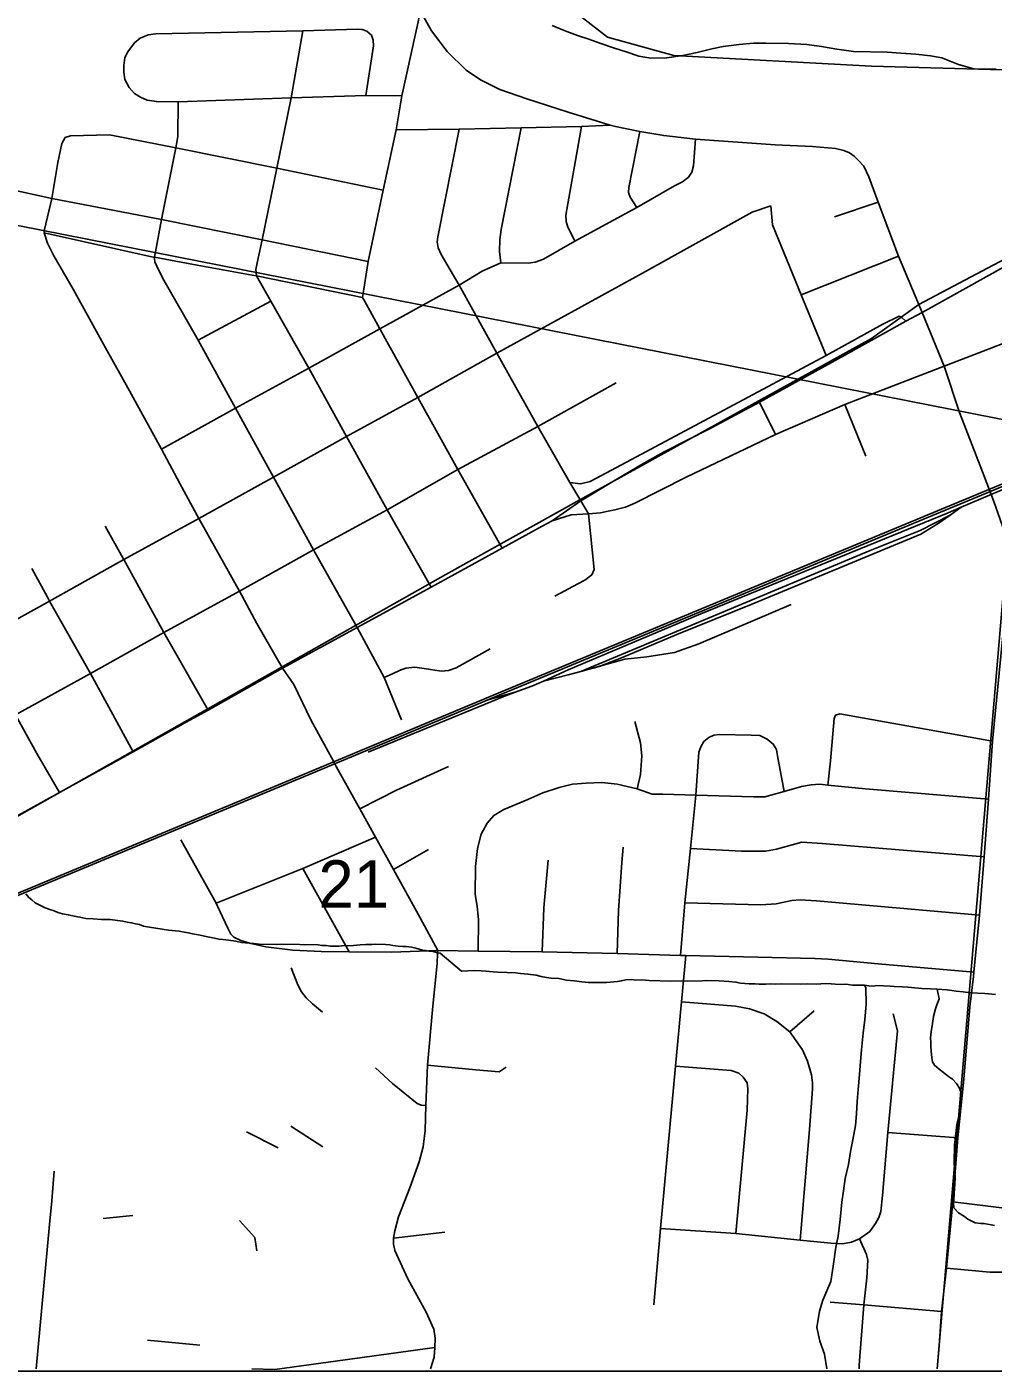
# Model space of a CAD drawing. Extents: x 0 to 34, y 0 to 22.
# Drawn here: x 5.806 to 6.657, y 14 to 15.184 of the extents above; entities that cross this region are included whole.
import ezdxf

# ---------------------------------------------------------------- set-up
doc = ezdxf.new("R2010")
doc.units = 0
for name, color, linetype in [('GM_X_City_Street', 7, 'Continuous'), ('GM_X_County_Road', 7, 'Continuous'), ('GM_X_Major_River', 7, 'Continuous'), ('GM_X_Minor_River', 7, 'Continuous'), ('GM_X_Rail_Line', 7, 'Continuous'), ('GM_X_Section', 7, 'Continuous'), ('GM_X_Section_Text', 7, 'Continuous'), ('SH_Data', 7, 'Continuous')]:
    doc.layers.add(name, color=color, linetype=linetype)

msp = doc.modelspace()

# ---------------------------------------------------------------- linework, layer by layer
at = {"layer": 'GM_X_City_Street'}
for p, q in [((6.5177, 15.017), (6.5561, 15.0299)), ((5.8215, 15.0029), (5.9175, 14.9815)), ((6.4882, 14.9483), (6.574, 14.9822)), ((5.9562, 14.9744), (6.0046, 14.9656)), ((5.9569, 14.9084), (6.0211, 14.9426)), ((6.4657, 14.8253), (6.4514, 14.8537)), ((6.5453, 14.8062), (6.5268, 14.8515)), ((5.8895, 14.7186), (5.8752, 14.7444)), ((5.8243, 14.6819), (5.8105, 14.7072)), ((6.5222, 14.579), (6.6568, 14.555)), ((6.129, 14.442), (6.16, 14.4597)), ((6.0901, 14.3694), (6.0491, 14.4428)), ((6.4781, 14.2988), (6.4996, 14.3175)), ((6.0387, 14.2159), (6.0669, 14.1975)), ((5.9996, 14.2109), (6.0275, 14.1967)), ((6.5647, 14.2103), (6.6263, 14.2054)), ((5.8734, 14.1345), (5.8996, 14.1371)), ((6.1291, 14.117), (6.1743, 14.1224)), ((5.9123, 14.0272), (5.9584, 14.0229))]:
    msp.add_line(p, q, dxfattribs=at)
for points in [[(6.2249, 14.7251), (6.1857, 14.7943), (6.1505, 14.8578), (6.1171, 14.9182), (6.1034, 14.9431), (6.1017, 14.9458), (6.1069, 14.9777), (6.1199, 15.0406), (6.1313, 15.0935), (6.1364, 15.1237), (6.153, 15.1983)], [(6.3248, 15.0966), (6.32, 15.0976), (6.283, 15.1092), (6.2466, 15.121), (6.2227, 15.1293), (6.2058, 15.1378), (6.193, 15.1462), (6.1764, 15.1625), (6.1626, 15.1807), (6.153, 15.1983)], [(5.8916, 15.1445), (5.8914, 15.1502), (5.8925, 15.1574), (5.8951, 15.1623), (5.9008, 15.1704), (5.906, 15.1745), (5.9131, 15.1773), (5.9197, 15.1782), (6.0493, 15.1809), (6.0974, 15.1822), (6.1015, 15.1819), (6.1055, 15.1805), (6.1096, 15.177), (6.1113, 15.1727), (6.1115, 15.1675), (6.1046, 15.1238)], [(6.1622, 14.6908), (6.1235, 14.7588), (6.0877, 14.8234), (6.0546, 14.8837), (6.0211, 14.9426), (6.0085, 14.9649), (6.0077, 14.9706), (6.009, 14.9763), (6.0134, 14.9966), (6.0262, 15.0599), (6.039, 15.1218), (6.0493, 15.1809)], [(5.8916, 15.1445), (5.8925, 15.1381), (5.8962, 15.1309), (5.9009, 15.1255), (5.9061, 15.1225), (5.9121, 15.1199), (5.9202, 15.1185), (5.9395, 15.1183), (6.039, 15.1218), (6.1046, 15.1238), (6.1364, 15.1237)], [(5.9186, 14.9803), (5.9185, 14.9813), (5.9246, 15.0145), (5.9373, 15.0778), (5.9385, 15.0841), (5.9391, 15.088), (5.9395, 15.1183)], [(5.8217, 15.0059), (5.828, 15.0331), (5.8335, 15.0647), (5.8368, 15.0815), (5.8399, 15.0868), (5.8445, 15.0882)], [(5.8445, 15.0882), (5.8788, 15.0892), (5.9373, 15.0778), (6.0262, 15.0599), (6.1199, 15.0406)], [(6.1313, 15.0935), (6.1869, 15.0941), (6.2415, 15.0953), (6.2948, 15.0966), (6.32, 15.0976)], [(6.301, 14.7554), (6.2942, 14.7667), (6.2843, 14.7828), (6.2561, 14.8323), (6.2201, 14.8968), (6.1869, 14.9569), (6.171, 14.9839), (6.1685, 14.9898), (6.1676, 14.995), (6.1682, 14.9994), (6.1869, 15.0941)], [(6.2236, 14.9763), (6.2224, 14.9863), (6.2229, 14.9971), (6.2238, 15.0059), (6.2415, 15.0953)], [(6.2889, 14.9955), (6.2852, 15.0028), (6.2826, 15.0079), (6.2811, 15.013), (6.2809, 15.0184), (6.2948, 15.0966)], [(6.6142, 14.8854), (6.5947, 14.9327), (6.574, 14.9822), (6.5561, 15.0299), (6.5479, 15.0523), (6.5435, 15.0616), (6.5387, 15.0667), (6.5348, 15.0705), (6.5308, 15.0735), (6.5257, 15.0754), (6.5184, 15.0771), (6.4982, 15.0789), (6.4652, 15.0805), (6.395, 15.0853), (6.3672, 15.0885), (6.346, 15.0921), (6.3248, 15.0966)], [(6.3435, 15.0251), (6.3377, 15.0343), (6.3361, 15.0385), (6.3364, 15.0428), (6.346, 15.0921)], [(5.9246, 14.8122), (5.9898, 14.8483), (6.0546, 14.8837), (6.1171, 14.9182), (6.1869, 14.9569), (6.2071, 14.969), (6.2236, 14.9763), (6.2476, 14.9761), (6.2538, 14.9769), (6.2611, 14.9796), (6.2889, 14.9955), (6.3435, 15.0251), (6.3766, 15.0442), (6.3836, 15.0479), (6.3891, 15.052), (6.3919, 15.0564), (6.3935, 15.062), (6.395, 15.0853)], [(6.9067, 15.0855), (6.8847, 15.0834), (6.8704, 15.082), (6.8594, 15.0779), (6.7869, 15.0396), (6.7593, 15.0237), (6.7279, 15.0059), (6.687, 14.9841), (6.5947, 14.9327), (6.5803, 14.9251), (6.5268, 14.8951), (6.4514, 14.8537), (6.4086, 14.8309), (6.3668, 14.8095), (6.3502, 14.8001), (6.3244, 14.7851), (6.2942, 14.7667), (6.2688, 14.7491)], [(5.7623, 15.0474), (5.828, 15.0331), (5.9246, 15.0145), (6.0134, 14.9966), (6.1069, 14.9777)], [(5.7606, 14.6422), (5.8261, 14.6785), (5.8914, 14.7152), (5.9576, 14.7513), (6.0234, 14.7875), (6.0877, 14.8234), (6.1505, 14.8578), (6.2201, 14.8968), (6.3483, 14.9674), (6.445, 15.0211), (6.4614, 15.0267)], [(6.5101, 14.8947), (6.4882, 14.9483), (6.4631, 15.01), (6.4614, 15.0267)], [(6.0313, 14.6194), (6.0088, 14.6588), (5.9933, 14.6873), (5.9576, 14.7513), (5.9409, 14.7821), (5.9246, 14.8122), (5.8966, 14.8637), (5.8753, 14.9015), (5.8468, 14.9533), (5.83, 14.9826), (5.8242, 14.9937), (5.8215, 15.0029), (5.8217, 15.0059)], [(5.9175, 14.9815), (5.9185, 14.9813), (5.9562, 14.9744)], [(6.0971, 14.6553), (6.0587, 14.7237), (6.0234, 14.7875), (5.9898, 14.8483), (5.9569, 14.9084), (5.9256, 14.9633), (5.9205, 14.9735), (5.9189, 14.9772), (5.9186, 14.9803)], [(6.0046, 14.9656), (6.0085, 14.9649), (6.1017, 14.9458)], [(6.2843, 14.7828), (6.2938, 14.7818), (6.3022, 14.7838), (6.33, 14.7984), (6.5101, 14.8947), (6.5603, 14.9223), (6.5746, 14.9294), (6.5768, 14.9284), (6.5803, 14.9251)], [(6.6399, 14.3476), (6.6404, 14.3515), (6.6452, 14.4018), (6.6495, 14.453), (6.6532, 14.5039), (6.6568, 14.555), (6.667, 14.6598), (6.6712, 14.7093), (6.6714, 14.7157), (6.6708, 14.7242), (6.6673, 14.7393), (6.6579, 14.7661), (6.648, 14.7923), (6.6276, 14.8447), (6.6142, 14.8854)], [(5.6319, 14.4874), (5.6747, 14.5115), (5.717, 14.535), (5.76, 14.5587), (5.7961, 14.5781), (5.8621, 14.6147), (5.9268, 14.6507), (5.9933, 14.6873), (6.0587, 14.7237), (6.1235, 14.7588), (6.1857, 14.7943), (6.2561, 14.8323), (6.3253, 14.8707)], [(6.2713, 14.6828), (6.2916, 14.6936), (6.2977, 14.697), (6.3038, 14.7015), (6.3059, 14.7063), (6.301, 14.7554)], [(5.9657, 14.5824), (5.9268, 14.6507), (5.8914, 14.7152), (5.8895, 14.7186)], [(5.8999, 14.5457), (5.8621, 14.6147), (5.8261, 14.6785), (5.8243, 14.6819)], [(6.1362, 14.5739), (6.1208, 14.6111), (6.0971, 14.6553)], [(6.1208, 14.6111), (6.1289, 14.6147), (6.1345, 14.6174), (6.14, 14.6193), (6.1478, 14.6202), (6.1561, 14.619), (6.1711, 14.6166), (6.1775, 14.6173), (6.1843, 14.6195), (6.2143, 14.6364)], [(6.0787, 14.5327), (6.0764, 14.5369), (6.0563, 14.5739), (6.0412, 14.605), (6.0313, 14.6194)], [(6.3438, 14.513), (6.3466, 14.5256), (6.3479, 14.5421), (6.3468, 14.5536), (6.3418, 14.5722)], [(6.5117, 14.5162), (6.5141, 14.5377), (6.5174, 14.575), (6.5186, 14.578), (6.5222, 14.579)], [(6.3955, 14.5075), (6.3982, 14.5453), (6.3997, 14.55), (6.4024, 14.5548), (6.407, 14.5583), (6.4114, 14.5603), (6.4162, 14.5608), (6.4442, 14.5604), (6.4517, 14.56), (6.4584, 14.5568), (6.4636, 14.5524), (6.4664, 14.5476), (6.4674, 14.542), (6.4732, 14.5106)], [(6.1679, 14.3686), (6.168, 14.3705), (6.1527, 14.3993), (6.129, 14.442), (6.1131, 14.4705), (6.0995, 14.4955), (6.0787, 14.5327)], [(6.0995, 14.4955), (6.1316, 14.5117), (6.1775, 14.5328)], [(6.2038, 14.3701), (6.2041, 14.3979), (6.2028, 14.4093), (6.2009, 14.4203), (6.2014, 14.4445), (6.2032, 14.4603), (6.2064, 14.473), (6.2116, 14.4827), (6.2174, 14.4895), (6.2263, 14.4947), (6.2473, 14.5037), (6.2605, 14.5094), (6.2751, 14.5143), (6.2867, 14.517), (6.2988, 14.5181), (6.3127, 14.5185), (6.3261, 14.5172), (6.3438, 14.513), (6.357, 14.5084), (6.3664, 14.5082), (6.3955, 14.5075), (6.4462, 14.5059), (6.4562, 14.5061), (6.4646, 14.5083), (6.4732, 14.5106), (6.4884, 14.5152), (6.4969, 14.5165), (6.5046, 14.5171), (6.5117, 14.5162), (6.5449, 14.5129), (6.6532, 14.5039)], [(6.3819, 14.3663), (6.3856, 14.4127), (6.3907, 14.4604), (6.3955, 14.5075)], [(5.9741, 14.4096), (5.9729, 14.4122), (5.9418, 14.4682)], [(5.9729, 14.4122), (6.0491, 14.4428), (6.1131, 14.4705)], [(6.3262, 14.3679), (6.3274, 14.4057), (6.3302, 14.448), (6.3313, 14.4616)], [(6.3907, 14.4604), (6.4356, 14.4581), (6.4569, 14.458), (6.4666, 14.46), (6.4751, 14.4622), (6.4887, 14.4659), (6.5067, 14.4648), (6.6495, 14.453)], [(6.2602, 14.3694), (6.2616, 14.4083), (6.2652, 14.4503)], [(6.3856, 14.4127), (6.4526, 14.4109), (6.4663, 14.4118), (6.4801, 14.4145), (6.4873, 14.4152), (6.5016, 14.4144), (6.6452, 14.4018)], [(5.9946, 14.3793), (5.9883, 14.3823), (5.9857, 14.3851), (5.9831, 14.3903), (5.9741, 14.4096)], [(5.9946, 14.3793), (6.0033, 14.3768), (6.0167, 14.3738), (6.0405, 14.371), (6.0654, 14.3696), (6.0901, 14.3694), (6.1272, 14.3691), (6.168, 14.3705), (6.2038, 14.3701), (6.2602, 14.3694), (6.3262, 14.3679), (6.3819, 14.3663), (6.3867, 14.3662), (6.4499, 14.3648), (6.5003, 14.3634), (6.5121, 14.3629), (6.5559, 14.3588), (6.6404, 14.3515)], [(6.1617, 14.0019), (6.165, 14.0123), (6.1655, 14.0208), (6.1658, 14.0289), (6.1647, 14.037), (6.1578, 14.0518), (6.1416, 14.0812), (6.1303, 14.1063), (6.129, 14.1118), (6.1291, 14.117), (6.1303, 14.1237), (6.1336, 14.1359), (6.1434, 14.1615), (6.1518, 14.1844), (6.1553, 14.1975), (6.1571, 14.2121), (6.1576, 14.2341), (6.159, 14.2696), (6.1637, 14.3214), (6.1675, 14.359), (6.1679, 14.3686)], [(6.3585, 14.0584), (6.3642, 14.1257), (6.3776, 14.2687), (6.3829, 14.3253), (6.3867, 14.3662)], [(6.0388, 14.3554), (6.0447, 14.3403), (6.0479, 14.3341), (6.0523, 14.3288), (6.0578, 14.3235), (6.0665, 14.3163)], [(6.6081, 14.0019), (6.6097, 14.0223), (6.6118, 14.0525), (6.6163, 14.0907), (6.6217, 14.149), (6.6263, 14.2054), (6.6316, 14.2572), (6.6368, 14.321), (6.6399, 14.3476)], [(6.4873, 14.1155), (6.4957, 14.2129), (6.4982, 14.2484), (6.4982, 14.2539), (6.4972, 14.2611), (6.4939, 14.2732), (6.4894, 14.283), (6.4781, 14.2988), (6.4669, 14.308), (6.4555, 14.3148), (6.4428, 14.3193), (6.4303, 14.3214), (6.3829, 14.3253)], [(6.3642, 14.1257), (6.4308, 14.1211), (6.4873, 14.1155), (6.5144, 14.1128), (6.5246, 14.1121), (6.5325, 14.1136), (6.5396, 14.1164), (6.5487, 14.1231), (6.5538, 14.1302), (6.5566, 14.1353), (6.5583, 14.1406), (6.5599, 14.1548), (6.5647, 14.2103), (6.573, 14.2997), (6.5694, 14.3147)], [(6.1131, 14.2672), (6.1283, 14.2535), (6.1499, 14.2359), (6.1534, 14.2344), (6.1576, 14.2341)], [(6.159, 14.2696), (6.2015, 14.2653), (6.2223, 14.2638), (6.2284, 14.2678)], [(6.4308, 14.1211), (6.4405, 14.2298), (6.4413, 14.2488), (6.4405, 14.2539), (6.437, 14.2591), (6.4333, 14.2626), (6.4266, 14.2649), (6.3776, 14.2687)], [(5.8142, 14.0019), (5.826, 14.1293), (5.8281, 14.1501), (5.8303, 14.1763)], [(6.6217, 14.149), (6.7966, 14.1277), (6.7983, 14.1272)], [(5.9933, 14.1326), (6.0068, 14.1178), (6.0086, 14.106)], [(6.5393, 14.0019), (6.5394, 14.0053), (6.5435, 14.0584), (6.546, 14.0823), (6.5469, 14.0978), (6.5459, 14.1026), (6.5396, 14.1164)], [(6.6163, 14.0907), (6.6545, 14.0873), (6.6654, 14.0872), (6.6734, 14.0884), (6.6933, 14.0946), (6.7014, 14.0949), (6.7482, 14.0907), (6.7534, 14.0894), (6.7583, 14.0868), (6.7638, 14.08)], [(6.5137, 14.0606), (6.5435, 14.0584), (6.6118, 14.0525)], [(6.0044, 14.002), (6.0246, 14.0014), (6.1655, 14.0208)]]:
    msp.add_lwpolyline(points, dxfattribs=at)
at = {"layer": 'GM_X_County_Road'}
for points in [[(6.3183, 14.7576), (6.3242, 14.7589), (6.3334, 14.7613), (6.3417, 14.7648), (6.387, 14.7877), (6.4657, 14.8253), (6.5268, 14.8515), (6.6142, 14.8854), (6.6921, 14.9153)], [(6.26, 14.7443), (6.2688, 14.7491), (6.2856, 14.7543), (6.301, 14.7554), (6.3114, 14.7562), (6.3183, 14.7576)], [(5.946, 14.5714), (5.9657, 14.5824), (6.0313, 14.6194), (6.0971, 14.6553), (6.1622, 14.6908), (6.2249, 14.7251), (6.26, 14.7443)], [(5.7198, 14.7161), (5.7268, 14.7035), (5.7432, 14.6736), (5.7606, 14.6422), (5.7811, 14.6051), (5.7961, 14.5781), (5.8149, 14.5442), (5.8348, 14.5098)], [(5.3074, 14.2462), (5.3154, 14.251), (5.329, 14.2582), (5.3473, 14.2671), (5.4124, 14.2985), (5.4668, 14.3252), (5.5266, 14.354), (5.5858, 14.3822), (5.6268, 14.4024), (5.6685, 14.423), (5.7094, 14.4428), (5.7337, 14.4547), (5.7485, 14.4622), (5.8348, 14.5098), (5.8999, 14.5457), (5.946, 14.5714)]]:
    msp.add_lwpolyline(points, dxfattribs=at)
at = {"layer": 'GM_X_Major_River'}
msp.add_lwpolyline([(6.2688, 15.1856), (6.2794, 15.1812), (6.2911, 15.1768), (6.3012, 15.1735), (6.311, 15.1699), (6.3238, 15.1655), (6.334, 15.1622), (6.3453, 15.1586), (6.3559, 15.1569), (6.37, 15.157), (6.384, 15.159), (6.3966, 15.1618), (6.4096, 15.1649), (6.4195, 15.167), (6.4335, 15.1687), (6.4461, 15.17), (6.4571, 15.1701), (6.4772, 15.1697), (6.4931, 15.1687), (6.506, 15.1669), (6.5196, 15.1647), (6.5343, 15.1625), (6.5639, 15.162), (6.5761, 15.1613), (6.5893, 15.1603), (6.6022, 15.1589), (6.612, 15.1572), (6.6267, 15.1512), (6.6403, 15.1475), (6.6498, 15.147), (6.66, 15.1472)], dxfattribs=at)
at = {"layer": 'GM_X_Minor_River'}
for points in [[(5.8053, 14.4205), (5.8079, 14.4174), (5.8105, 14.4151), (5.8135, 14.4127), (5.818, 14.4103), (5.8222, 14.4083), (5.8263, 14.4067), (5.8301, 14.4055), (5.8335, 14.4042), (5.8376, 14.403), (5.8426, 14.4021), (5.8479, 14.4008), (5.8528, 14.4), (5.8581, 14.3987), (5.8646, 14.3985), (5.8718, 14.398), (5.8794, 14.3978), (5.8859, 14.3969), (5.8908, 14.3964), (5.8946, 14.3955), (5.8984, 14.3951), (5.9018, 14.3942), (5.9053, 14.3934), (5.909, 14.3921), (5.914, 14.3912), (5.931, 14.3885), (5.9402, 14.3876)], [(5.9402, 14.3876), (5.9447, 14.3867), (5.9485, 14.3862), (5.9519, 14.3854), (5.9572, 14.3845), (5.9641, 14.3828), (5.9671, 14.3823), (5.9713, 14.3815), (5.9751, 14.3806), (5.9789, 14.3802), (5.9838, 14.3797), (5.9903, 14.3787), (5.9952, 14.3775), (6.002, 14.3769), (6.0062, 14.3768), (6.0108, 14.3763), (6.0264, 14.376), (6.0302, 14.3762), (6.0626, 14.3755), (6.066, 14.375), (6.0698, 14.3749), (6.0733, 14.3744), (6.0809, 14.3743), (6.0836, 14.3746), (6.087, 14.3749), (6.0904, 14.3748), (6.0939, 14.3751), (6.0969, 14.3754), (6.0996, 14.3757), (6.1046, 14.376), (6.1099, 14.3758), (6.1129, 14.3761), (6.1221, 14.3759), (6.1259, 14.3755), (6.1285, 14.375), (6.1331, 14.3745), (6.1373, 14.374), (6.1403, 14.374), (6.1449, 14.3735), (6.1487, 14.3726), (6.1547, 14.3709), (6.1574, 14.3705), (6.1604, 14.37), (6.1639, 14.3696), (6.1669, 14.3687), (6.1703, 14.3683)], [(6.1703, 14.3683), (6.189, 14.3524), (6.1947, 14.3527), (6.2008, 14.3529), (6.2062, 14.3528), (6.2103, 14.3523), (6.2168, 14.3517), (6.221, 14.3516), (6.2293, 14.3511), (6.2365, 14.3509), (6.2411, 14.3504), (6.2475, 14.3498), (6.2547, 14.3489), (6.2593, 14.3477), (6.2638, 14.3468), (6.268, 14.3463), (6.2748, 14.3458), (6.2816, 14.3444), (6.2881, 14.3439), (6.2949, 14.343), (6.301, 14.3424), (6.3166, 14.3424), (6.3265, 14.3433), (6.3299, 14.344), (6.3337, 14.3447), (6.3391, 14.3449), (6.3425, 14.3445), (6.3478, 14.3447), (6.3543, 14.3442), (6.3733, 14.3437), (6.3851, 14.3438), (6.3885, 14.3437), (6.4014, 14.3438), (6.4048, 14.3441), (6.4159, 14.3438), (6.4246, 14.3432), (6.4307, 14.3427), (6.4348, 14.3418), (6.4424, 14.3412), (6.4477, 14.3411), (6.4512, 14.341), (6.4572, 14.3409), (6.4611, 14.3411), (6.4656, 14.341), (6.4706, 14.3413), (6.488, 14.3409), (6.4938, 14.3411), (6.5017, 14.3409), (6.5055, 14.3412), (6.5097, 14.3415), (6.5147, 14.3413), (6.5181, 14.3409), (6.5238, 14.3407), (6.5276, 14.341), (6.5333, 14.3401), (6.5439, 14.3399), (6.5477, 14.3394), (6.5519, 14.3393), (6.5549, 14.3396), (6.5667, 14.3393), (6.5701, 14.3388), (6.5774, 14.3387), (6.5823, 14.3382), (6.5853, 14.3381), (6.5944, 14.3371), (6.602, 14.3369), (6.6081, 14.3364), (6.6123, 14.3363), (6.6168, 14.3358), (6.621, 14.3353), (6.6248, 14.3348), (6.6309, 14.3343), (6.6373, 14.3334), (6.6499, 14.3327), (6.6593, 14.3317)], [(6.5439, 14.3399), (6.5452, 14.3379), (6.5456, 14.323), (6.5442, 14.3097), (6.5429, 14.2976), (6.5414, 14.2832), (6.5405, 14.2729), (6.5395, 14.2612), (6.5385, 14.2482), (6.5375, 14.2376), (6.5369, 14.2266), (6.536, 14.2163), (6.5338, 14.2038), (6.5317, 14.1936), (6.53, 14.1819), (6.5271, 14.1697), (6.5254, 14.1587), (6.524, 14.1489), (6.5226, 14.1337), (6.5208, 14.1189), (6.5187, 14.1091), (6.5165, 14.0924), (6.5143, 14.0791), (6.5072, 14.0625), (6.5043, 14.0527), (6.5021, 14.0383), (6.5046, 14.0264), (6.5089, 14.0149), (6.5109, 14.0019)], [(6.6081, 14.3364), (6.6098, 14.328), (6.6078, 14.3227), (6.6065, 14.3193), (6.6049, 14.3125), (6.6039, 14.3064), (6.6026, 14.2989), (6.6021, 14.2936), (6.6024, 14.2894), (6.6023, 14.2859), (6.6026, 14.2821), (6.6032, 14.276), (6.6039, 14.2726), (6.6057, 14.2695), (6.6098, 14.266), (6.6135, 14.2632), (6.618, 14.2597), (6.6214, 14.2573), (6.6251, 14.2535), (6.6276, 14.2492), (6.6291, 14.245), (6.6297, 14.24), (6.6287, 14.2305), (6.6258, 14.22), (6.6253, 14.2169), (6.6243, 14.2071), (6.6239, 14.2037), (6.6234, 14.1995), (6.623, 14.1832), (6.6232, 14.1786), (6.6238, 14.1714), (6.6236, 14.1641), (6.6232, 14.1611), (6.6231, 14.1558), (6.6226, 14.1512), (6.6225, 14.1482), (6.6228, 14.144), (6.6268, 14.1394), (6.6321, 14.1362), (6.6351, 14.1338), (6.6414, 14.1306), (6.6464, 14.1301), (6.6494, 14.1301), (6.6585, 14.1283)]]:
    msp.add_lwpolyline(points, dxfattribs=at)
at = {"layer": 'GM_X_Rail_Line'}
for p, q in [((6.6293, 14.7613), (6.6194, 14.7542)), ((6.3036, 14.6191), (6.3117, 14.6214)), ((6.2114, 14.591), (6.2363, 14.5981))]:
    msp.add_line(p, q, dxfattribs=at)
for points in [[(5.0173, 14.0019), (5.072, 14.0644), (5.1295, 14.1143), (5.176, 14.1513), (5.2792, 14.2282), (5.3136, 14.2527), (5.4907, 14.3356), (5.7836, 14.4807), (6.1751, 14.7018), (6.2931, 14.7677), (6.5502, 14.9097), (6.5918, 14.9396), (6.8599, 15.0815), (6.9063, 15.1008), (7.0305, 15.1642), (7.127, 15.2232), (7.2771, 15.3236), (7.3717, 15.417), (7.5681, 15.606)], [(5.7904, 14.4179), (6.0539, 14.5273), (6.2249, 14.5987), (6.655, 14.7772), (7.1284, 14.974), (7.1666, 14.9925), (7.2004, 15.0117), (7.2218, 15.0246), (7.2404, 15.037), (7.2637, 15.0539)], [(5.7911, 14.4161), (6.0547, 14.5256), (6.2256, 14.597), (6.6557, 14.7754), (7.1292, 14.9723), (7.1675, 14.9908), (7.2014, 15.0101), (7.2228, 15.0229), (7.2415, 15.0354), (7.2648, 15.0523)], [(6.7052, 14.7936), (6.6889, 14.7865), (6.6293, 14.7613)], [(6.6293, 14.7613), (6.6176, 14.7563), (6.3999, 14.6672), (6.2829, 14.6179), (6.2612, 14.608)], [(6.294, 14.6164), (6.5489, 14.7229), (6.5931, 14.7406), (6.6194, 14.7542)], [(6.6194, 14.7542), (6.609, 14.7469), (6.5936, 14.7373), (6.4442, 14.6753), (6.3788, 14.6489), (6.33, 14.6284), (6.3117, 14.6214)], [(6.3117, 14.6214), (6.3328, 14.6273), (6.3522, 14.6292), (6.3766, 14.6332), (6.3981, 14.6409), (6.4793, 14.6755)], [(6.294, 14.6164), (6.2831, 14.6134), (6.2612, 14.608)], [(6.3117, 14.6214), (6.3114, 14.6212), (6.3036, 14.6191), (6.294, 14.6164)], [(6.2612, 14.608), (6.251, 14.6034), (6.2363, 14.5981)], [(6.2363, 14.5981), (6.2263, 14.5945), (6.1069, 14.5454)]]:
    msp.add_lwpolyline(points, dxfattribs=at)
at = {"layer": 'GM_X_Section'}
msp.add_lwpolyline([(5.6244, 15.716), (6.1384, 15.8534), (6.2006, 15.8442), (6.2014, 15.8437), (6.2528, 15.8208), (6.2891, 15.7943), (6.3063, 15.7629), (6.3186, 15.7336), (6.3337, 15.6912), (6.344, 15.6551), (6.3366, 15.6033), (6.3107, 15.5299), (6.2685, 15.4432), (6.2444, 15.4077), (6.2145, 15.3681), (6.2186, 15.3071), (6.2755, 15.2079), (6.3177, 15.1753), (6.376, 15.1591), (6.5501, 15.1498), (6.7178, 15.1451), (6.679, 14.8357), (5.5653, 15.0552)], close=True, dxfattribs=at)
for points in [[(6.6081, 14.0019), (6.679, 14.8357), (7.7155, 15.1965), (7.6347, 14.2379), (7.0538, 14.0019)], [(5.672, 14.0019), (5.4797, 14.0411), (5.5231, 14.5424), (5.6709, 14.6936), (5.554, 14.8728), (5.5653, 15.0552), (6.679, 14.8357), (6.6081, 14.0019)]]:
    msp.add_lwpolyline(points, dxfattribs=at)
at = {"layer": 'SH_Data'}
msp.add_line((2, 14), (9, 14), dxfattribs=at)

# ---------------------------------------------------------------- texts
at = {"layer": 'GM_X_Section_Text'}
msp.add_text('21', height=0.04186, rotation=0, dxfattribs=at).set_placement((6.0629, 14.4082))

doc.saveas('drawing.dxf')
